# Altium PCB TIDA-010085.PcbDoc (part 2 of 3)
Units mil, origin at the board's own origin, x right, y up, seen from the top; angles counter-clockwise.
Board outline 1968.5 x 2559.06 mil, 4 copper layers (Top Layer, Signal Layer 1, Signal Layer 2, Bottom Layer), stack 5.6 mil thick; 254 components, 133 nets, 771 pads, 156 vias.
Unrouted connection lines stored in the file: 2.
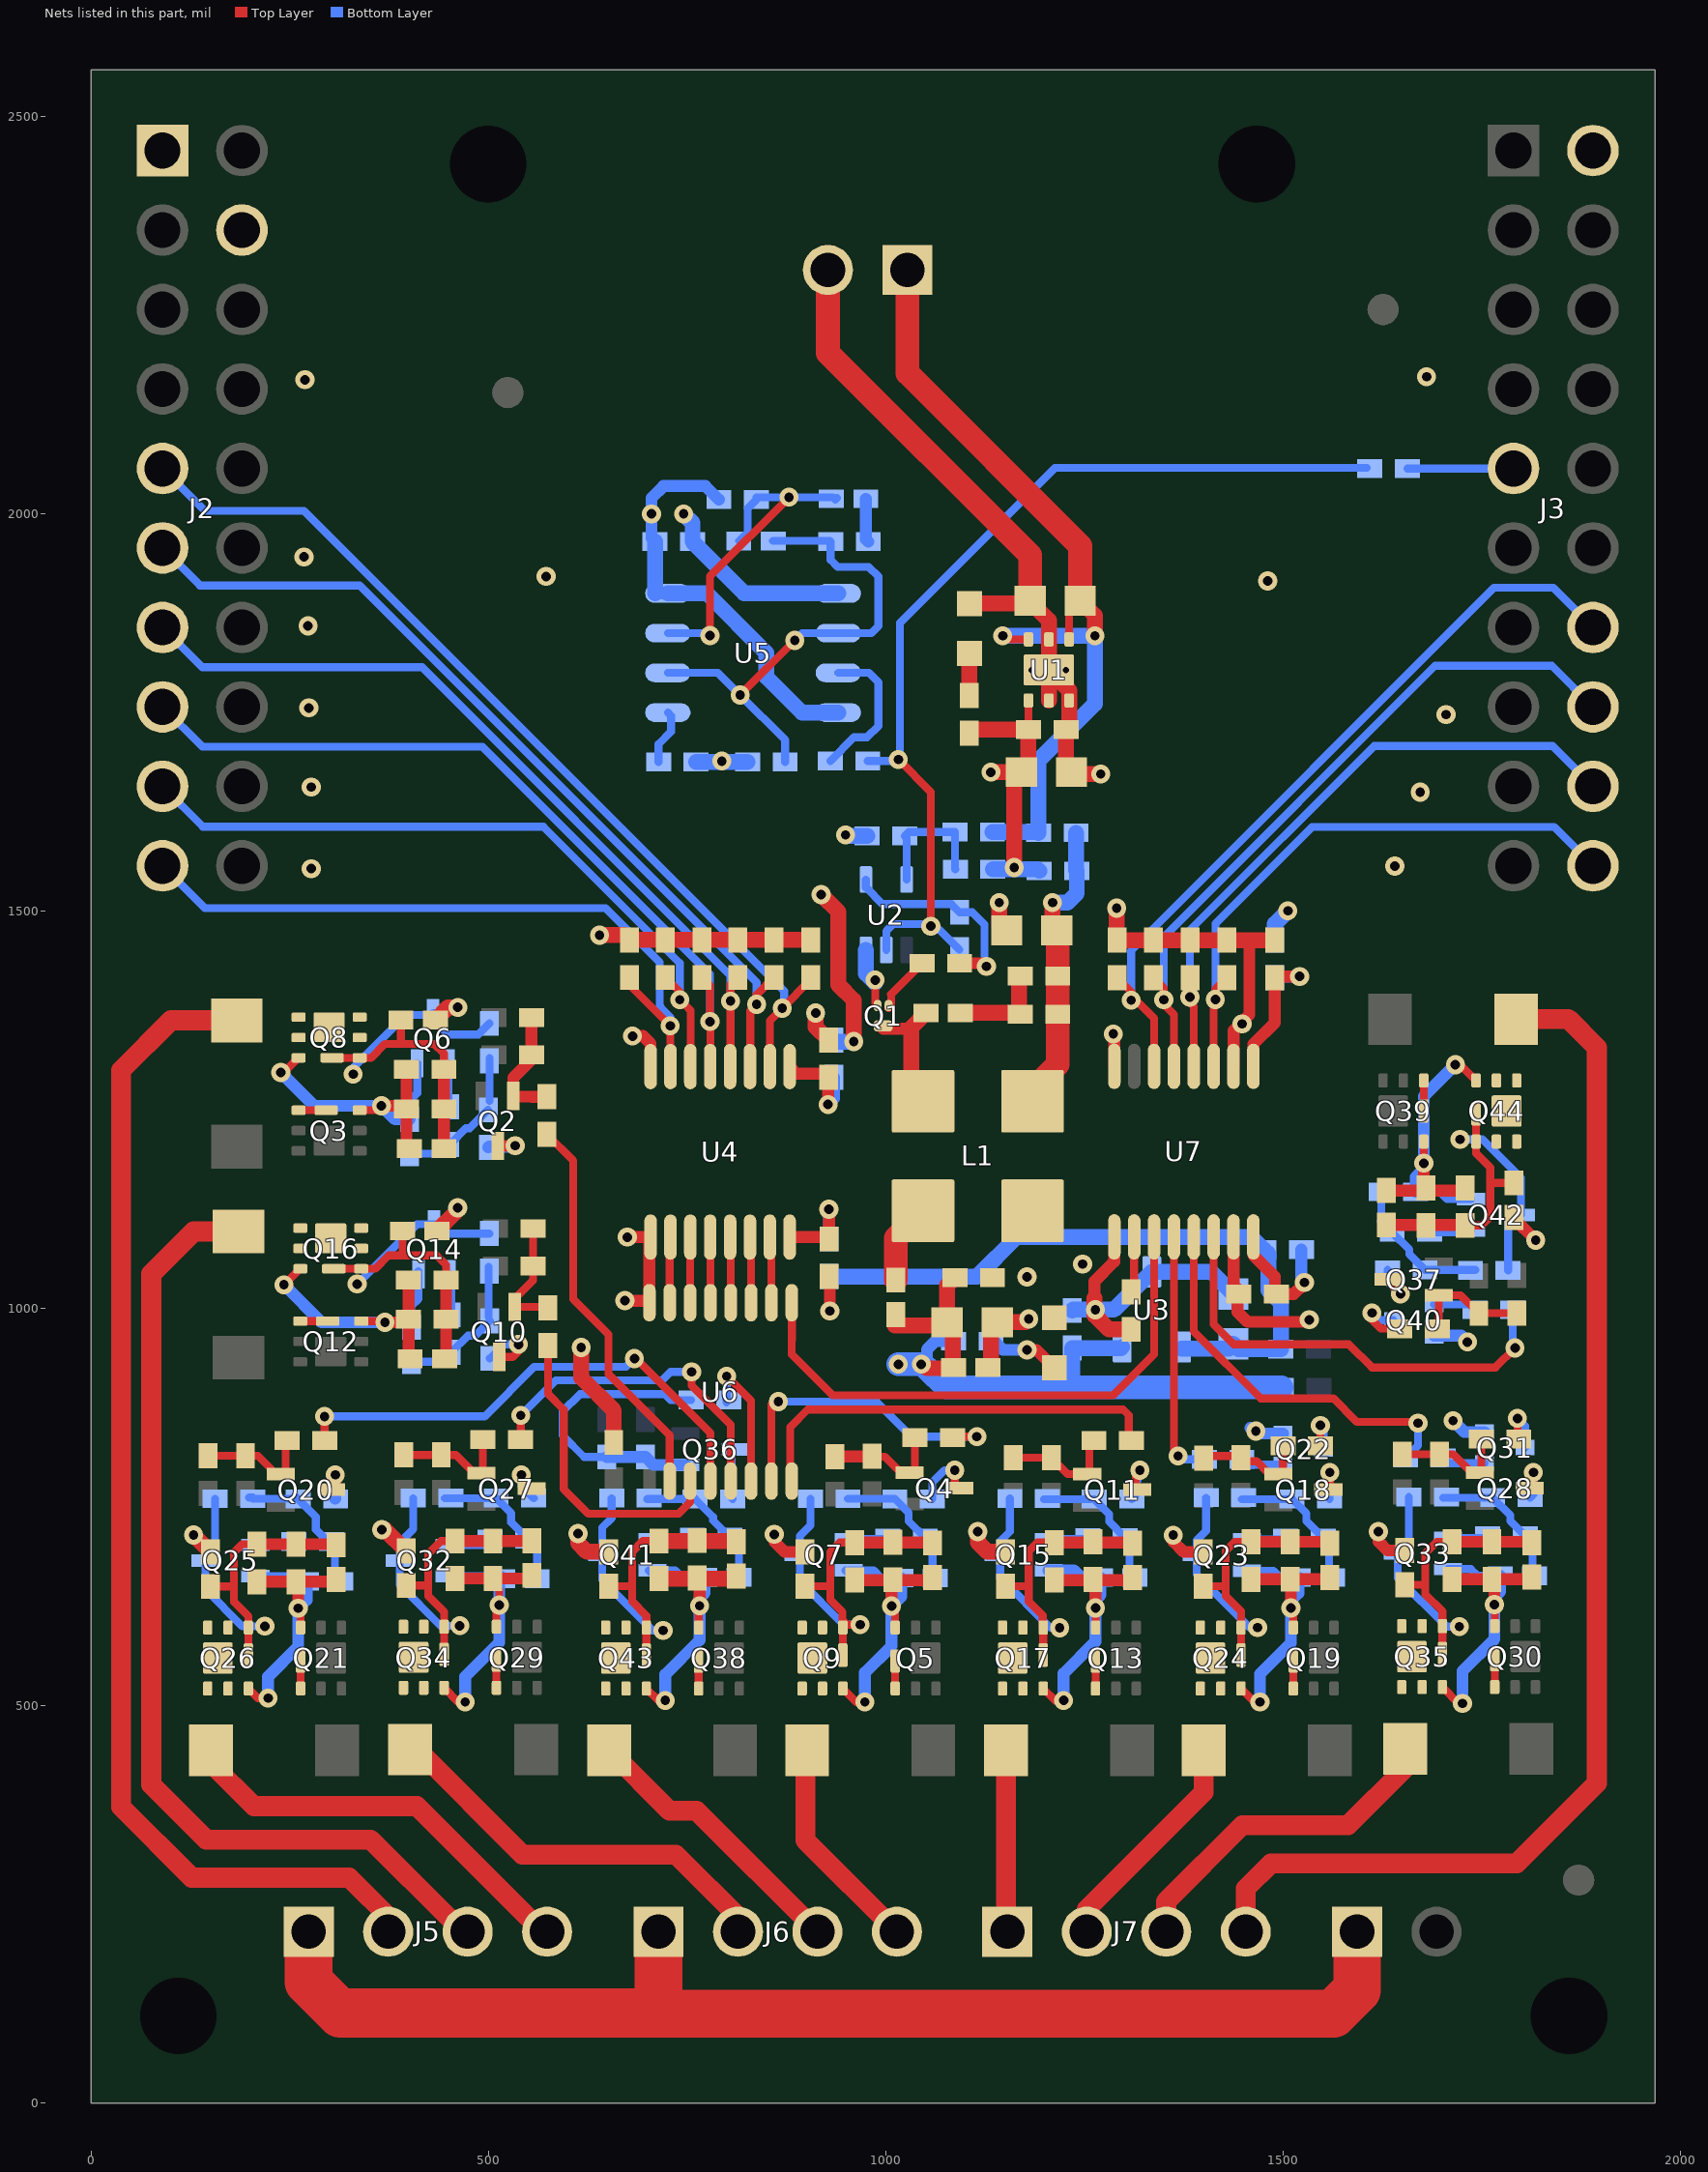
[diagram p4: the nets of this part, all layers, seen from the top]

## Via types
v1: diameter 24, hole 12, Top Layer to Bottom Layer, tented both sides, 144 vias
v2: diameter 40, hole 20, Top Layer to Bottom Layer, 10 vias
v3: diameter 19.68, hole 7.87, Top Layer to Bottom Layer, 2 vias

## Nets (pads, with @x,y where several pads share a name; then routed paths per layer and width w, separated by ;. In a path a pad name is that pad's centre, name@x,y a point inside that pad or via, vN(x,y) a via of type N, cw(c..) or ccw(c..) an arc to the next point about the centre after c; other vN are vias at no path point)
3V3: C3.1 C6.1 C12.2 J2.1 R1.2 R2.1 R10.1 R14.2 R16.2 R24.2 U1.1 U5.4 U5.8 | length 1179.7
  Top Layer w10: C6.1@1179.79,1728.71 U1.1@1179.79,1765.29
  Top Layer w20: v1(919,1521) 940.64,1499.36 940.64,1407.36 960,1388 v1(960,1336) ; R1.2@1105.38,1724.06 1110,1728.68 C6.1@1179.75,1728.68 C3.1@1179.75,1677.05 ; v1(1132.51,1675) C3.1@1151.81,1675 ; v1(1161.92,1555) 1161.92,1666.01 C3.1@1170.91,1675
  Bottom Layer w15: U5.8@709.89,1900 U5.8@726,1900 ; C12.2@709.89,1965 705.51,1969.38 v1(705.51,2000) 705.51,2020 720.51,2035 773.27,2035 R16.2@790.27,2018
  Bottom Layer w20: J2.1@90.08,2457.17 J2.1@101.3,2457.17 ; U5.8@709.89,1900 C12.2@709.89,1965 ; U5.8@726,1900 775,1900 850,1825 850,1795 895,1750 U5.4@940.57,1750 ; R14.2@935,1338.1 937.1,1336 v1(960,1336) ; R10.1@1134.97,1552.82 1191.29,1552.82 R2.1@1193.34,1550.76 ; R24.2@1489.83,1463.74 1489.83,1484.22 v1(1506.2,1500.58)
5V: C2.1 J1.1 R4.1 R11.1 U1.4 U1.6 | length 1100
  Top Layer w10: v1(1147.38,1846.68) 1151.99,1842.07 U1.6@1179.79,1842.07 ; U1.4@1230.97,1842.07 1230.97,1884.77 C2.1@1240.38,1894.18
  Top Layer w20: C2.1@1244.87,1890.68 1263.38,1872.18 v1(1263.38,1846.68)
  Top Layer w30: J1.1@1027.39,2307 1027.39,2177.24 1244.87,1959.77 C2.1@1244.87,1890.68
  Bottom Layer w20: R11.1@1134.48,1599.67 1191.54,1599.67 R4.1@1192.44,1598.76 1192.44,1690.19 1263.38,1761.12 v1(1263.38,1846.68) v1(1147.38,1846.68)
5V_ISO: C9.1 R9.2 R13.2 R25.2 U3.1 | length 839
  Bottom Layer w20: R13.2@929,1040.11 R13.2@928.73,1040.38 1115.38,1040.38 1165,1090 1460.39,1090 R25.2@1476.01,1074.38 1482,1068.39 1482,1023 1497.38,1007.62 R9.2@1497.38,949 1444.11,949 C9.1@1437.61,955.5 1431.86,949.76 U3.1@1372.4,949.76
12V_ISO: C1.2 C8.1 D1.1 D2.1 R3.2 R5.1 R8.1 U3.2 | length 881.7
  Top Layer w20: D1.1@1011.7,978.64 1073.34,978.64 C1.2@1077.5,982.8 ; v1@1052,925 D2.1@1084.36,925 ; D2.1@1085.35,925.98 D2.1@1084.36,925 ; R5.1@1087.24,1039.12 1077.5,1029.38 C1.2@1077.5,982.8 ; C1.2@1077.5,982.8 1084.36,975.94 D2.1@1084.36,925
  Bottom Layer w15: v1@1052,925 1052,948.53 1062.47,959 R3.2@1085.38,959
  Bottom Layer w20: 1233,901 1235,903 C8.1@1235,950.38 1296.22,950.38 U3.2@1297.6,951.76
  Bottom Layer w30: v1(1016,930) v1(1045,930) ; v1@1052,925 1076,901 1233,901 R8.1@1497.91,901
C: J4.1 J5.1 J6.1 | length 1934.1
  Top Layer w60: J5.1@274.13,216 274.13,152.78 311.91,115 ; 687.4,115 311.91,115 ; 714.24,141.84 J6.1@714.24,216 ; J4.1@1593.27,216 1593.27,142.67 1563.6,113 714.24,113 313.91,113 311.91,115
COIL-1: D12.1 J5.2 Q8.1 Q8.2 Q8.5 Q8.6 Q8.8 | length 1499.1
  Top Layer w25: D12.1@183.78,1362.45 183.39,1362.84 100.96,1362.84 38,1299.89 38,373 127,284 325,284 J5.2@379,230
COIL-2: D22.1 J5.3 Q16.1 Q16.2 Q16.5 Q16.6 Q16.8 | length 1248.4
  Top Layer w25: D22.1@185.83,1097.06 129.43,1097.06 76,1043.63 76,401 145,332 351.97,332 453.97,230 J5.3@479,230
COIL-3: D31.1 J5.4 Q26.1 Q26.2 Q26.5 Q26.6 Q26.8 | length 526.1
  Top Layer w25: D31.1@151.25,444.29 151.25,427.96 205.21,374 410,374 554,230 J5.4@579,230
COIL-4: D38.1 J6.2 Q34.1 Q34.2 Q34.5 Q34.6 Q34.8 | length 510.7
  Top Layer w25: D38.1@397.61,445.29 410.71,445.29 543,313 736.11,313 J6.2@819.11,230
COIL-5: D46.1 J6.3 Q43.1 Q43.2 Q43.5 Q43.6 Q43.8 | length 356.7
  Top Layer w25: D46.1@652.06,444.29 728.35,368 762.24,368 J6.3@914.24,216
COIL-6: D15.1 J6.4 Q9.1 Q9.2 Q9.5 Q9.6 Q9.8 | length 275.9
  Top Layer w25: D15.1@899.32,444.29 899.32,330.92 J6.4@1014.24,216
COIL-7: D23.1 J7.1 Q17.1 Q17.2 Q17.5 Q17.6 Q17.8 | length 229
  Top Layer w25: D23.1@1151.43,444.29 1151.43,217.7 J7.1@1153.13,216
COIL-8: D28.1 J7.2 Q24.1 Q24.2 Q24.5 Q24.6 Q24.8 | length 289.3
  Top Layer w25: J7.2@1253.13,216 1253.13,243.99 1400.32,391.18 D28.1@1400.32,444.29
COIL-9: D39.1 J7.3 Q35.1 Q35.2 Q35.5 Q35.6 Q35.8 | length 432.6
  Top Layer w25: J7.3@1353.13,216 1353.13,254.13 1448.86,349.86 1581.86,349.86 1653.78,421.78 D39.1@1653.78,446.11
COIL-10: D47.1 J7.4 Q44.1 Q44.2 Q44.5 Q44.6 Q44.8 | length 1596.3
  Top Layer w25: J7.4@1453.13,216 1453.13,270.13 1485,302 1794,302 1895,403 1895,1328.61 1859.01,1364.61 D47.1@1790.23,1364.61
GND: C2.2 C3.2 C4.2 C6.2 C7.2 C10.1 C12.1 C13.2 C14.2 C16.1 D3.1 J1.2 J2.4 J3.2 Q1.2 R18.1 R19.1 R20.1 R21.1 R22.1 R23.1 R28.1 R29.1 R30.1 R31.1 U1.2 U1.3 U1.5 U1.7@1205.38,1803.68 U2.3 U4.8 U5.1 U7.2 U7.8 | length 2187.6
  Top Layer w9.84: v1(986.83,1413.53) 986.83,1384.49 Q1.2@989.97,1381.35
  Top Layer w15: v1(681.57,1342.96) 694.96,1342.96 704.25,1333.67 704.25,1304.63 U4.8@704.3,1304.57 ; v1(1286.44,1345.67) 1287.78,1344.33 U7.8@1287.78,1304.82 ; U7.2@1437.78,1304.91 1437.78,1349.84 1457.8,1369.86 1457.8,1463.74
  Top Layer w20: v1(640,1470) 671.71,1470 R23.1@677.75,1463.96 R22.1@722.75,1463.96 R21.1@768.75,1463.96 R20.1@813.75,1463.96 R19.1@859.56,1463.96 R18.1@905.75,1463.96 ; v1(912,1372) 912,1354.29 C10.1@928.2,1338.1 ; D3.1@1105.38,1887.18 1175.38,1887.18 1179.88,1891.68 1205.38,1866.18 U1.5@1205.38,1842.07 U1.7@1205.38,1803.68 ; v1(1143,1511) 1143,1480.65 C4.2@1147.72,1475.92 ; U1.2@1205.38,1765.29 U1.7@1205.38,1803.68 ; v1(1270.7,1672.68) 1236.22,1672.68 C3.2@1233.9,1675 1227,1681.91 C6.2@1227,1728.68 1230.97,1732.65 U1.3@1230.97,1765.29 1230.97,1778.09 U1.7@1205.38,1803.68 ; v1(1290.83,1504) 1290.83,1464.1 R31.1@1291.2,1463.74 R30.1@1336.99,1463.74 R29.1@1383.2,1463.74 R28.1@1429.2,1463.74 1457.8,1463.74 C16.1@1489.83,1463.74
  Top Layer w30: J1.2@927.39,2307 927.39,2202.48 1181.88,1947.99 C2.2@1181.88,1890.68
  Bottom Layer w20: v1(745.89,2000) 757.13,1988.76 C12.1@757.13,1965 822.13,1900 U5.1@940.57,1900 ; C13.2@761.62,1688 C14.2@826.38,1688 ; v1(949.67,1596.12) 951.18,1594.61 C7.2@976.72,1594.61 ; U2.3@975.25,1451.32 975.25,1421.67 v1@986.83,1410.09
  other v1: 1448.63,1358.26 277.31,1553.63 1640.84,1556.85 1672.73,1649.98 277.31,1656.26 794,1689 1705.33,1747.55 274.31,1755.85 273.22,1858.99 1480.7,1915.64 572.73,1921.28 268.31,1945.85 269.31,2168.85 1680.7,2172.64
  other v3: 1183.72,1803.68 1227.03,1803.68
IN1: J2.19 R23.2 U4.7 | length 899.1
  Top Layer w10: R23.2@676.47,1415.44 R23.2@677.75,1416.72 677.75,1407.09 v1(729,1355.84) 729.3,1355.54 U4.7@729.3,1304.57 ; U4.7@729.8,1302.34 U4.7@729.8,1304.57
  Bottom Layer w10: J2.19@90.08,1557.17 143.26,1504 647.79,1504 715.88,1435.91 715.88,1381.25 717,1380.13 717,1378.81 729,1366.81 v1(729,1355.84)
IN2: J2.17 R22.2 U4.6 | length 899.5
  Top Layer w10: R22.2@722.75,1416.72 741,1398.47 v1(741,1388.75) ; v1@748,1382 754.8,1375.2 U4.6@754.8,1302.34
  Bottom Layer w10: J2.17@90.08,1657.17 140.84,1606.42 569.42,1606.42 741,1434.83 v1@741,1396.41
IN3: J2.15 R21.2 U4.5 | length 1006.5
  Top Layer w10: R21.2@768.75,1416.72 779,1406.47 v1(779,1361.2) ; U4.5@779.8,1302.34 v1@779.8,1361.2
  Bottom Layer w10: J2.15@90.08,1757.17 140.23,1707.03 492.85,1707.03 779,1420.88 v1(779,1361.2)
IN4: J2.13 R20.2 U4.4 | length 1046.4
  Top Layer w10: U4.4@804.8,1302.34 v1(804.8,1387) 804.8,1407.77 R20.2@813.75,1416.72
  Bottom Layer w10: J2.13@90.08,1857.17 140.26,1807 416.92,1807 804.8,1419.11 v1(804.8,1387)
IN5: J2.11 R19.2 U4.3 | length 1128.4
  Top Layer w10: U4.3@829.8,1302.34 829.8,1374.82 v1(837.76,1382.78) 837.76,1394.92 R19.2@859.56,1416.72
  Bottom Layer w10: J2.11@90.08,1957.17 137.26,1910 337.96,1910 837.76,1410.2 v1(837.76,1382.78)
IN6: J2.9 R18.2 U4.2 | length 1216.2
  Top Layer w10: U4.2@854.3,1304.57 854.3,1362.22 v1(870,1377.92) R18.2@905.75,1413.67 ; R18.2@905.75,1407.29 R18.2@905.75,1413.67 ; R18.2@905.75,1416.72 R18.2@905.75,1413.67
  Bottom Layer w10: J2.9@90.08,2057.17 143.59,2003.67 268.33,2003.67 872.32,1399.68 v1@872.32,1377.92
IN7: J3.14 R31.2 U7.6 | length 987.5
  Top Layer w10: R31.2@1291.2,1416.49 1309,1398.69 v1(1309,1388.13) 1314.87,1388.13 1337.78,1365.22 U7.6@1337.78,1304.91
  Bottom Layer w10: v1(1309,1388.13) 1309,1450.53 1765.47,1907 1840.26,1907 J3.14@1890.08,1857.17
IN8: J3.16 R30.2 U7.5 | length 903.9
  Top Layer w10: R30.2@1336.99,1416.49 1350,1403.48 v1(1350,1388.75) 1350,1382.78 1362.78,1370 U7.5@1362.78,1304.91
  Bottom Layer w10: v1(1350,1388.75) 1350,1467.49 1691.41,1808.9 1838.36,1808.9 J3.16@1890.08,1757.17
IN9: J3.18 R29.2 U7.4 | length 822.2
  Top Layer w10: R29.2@1383.2,1416.49 1382.83,1416.13 v1(1382.83,1392.12) 1382.83,1385.12 1387.78,1380.17 U7.4@1387.78,1304.91
  Bottom Layer w10: v1(1382.83,1392.12) 1382.83,1476.28 1614.46,1707.9 1839.36,1707.9 J3.18@1890.08,1657.17
IN10: J3.20 R28.2 U7.3 | length 750.4
  Top Layer w10: U7.3@1412.78,1304.91 v1@1412.78,1380.78 ; v1(1415,1388.97) 1415,1402.3 R28.2@1429.2,1416.49
  Bottom Layer w10: v1(1415,1388.97) 1415,1484.4 1536.6,1606 1841.26,1606 J3.20@1890.08,1557.17
ISO_GND: C1.1 C8.2 C9.2 C11.2 C15.2 C17.2 D2.2 D5.1 D10.1 D13.1 D18.1 D19.1 D26.1 D29.1 D34.1 D35.1 D42.1 D43.1 L1.4 Q22.2 Q31.2 Q40.2 R5.2 R27.2 U3.3 U4.9 U6.8 U7.9 U7.15 | length 1624.2
  Top Layer w15: v1(672,1010) 700.25,1010 U6.8@702.78,1007.47 702.78,1088.48 U4.9@704.3,1090.01 v1@675.01,1090.01 ; v1(860,716) 860,707 873.06,693.94 D13.1@898.65,693.94 ; C11.2@928.73,1040.38 929.89,1039.22 v1(929.89,997) ; R5.2@1134.48,1039.12 R5.2@1140.5,1039.12 ; 1262.98,1013.15 1262.98,1034.44 1287.78,1059.24 U7.9@1287.78,1090.25 ; v1@1362,719.29 v1(1362,715) 1362,706.94 1375,693.94 D26.1@1399.65,693.94 ; U7.15@1437.78,1090.25 1437.78,1029.82 1442.73,1024.87 1442.73,996.01 1455.43,983.31 1530.31,983.31 v1(1533,986) ; v1(1620,719.29) 1620,707.11 1631.35,695.77 D35.1@1653.11,695.77 ; D43.1@1792.53,1113 D43.1@1790.57,1114.95 1790.57,1113.43 v1(1818,1086)
  Top Layer w20: v1(129.25,715.27) D29.1@150.58,693.94 ; v1(366,722) 369.89,722 D34.1@396.94,694.94 ; D10.1@433.44,1363.12 449.44,1379.12 v1(461.78,1379.12) ; D18.1@435.48,1097.73 v1@458.16,1120.41 ; v1(613,717) 613,705 624.06,693.94 D42.1@651.4,693.94 ; v1(617,951) 617,913 658,872 C15.2@658,831.62 ; v1(1116,719.38) 1116,706 1128.06,693.94 D19.1@1150.76,693.94 ; D2.2@1132.51,925 1132.51,990.78 C1.1@1139.98,983.31 ; C1.1@1139.98,985.72 C1.1@1139.98,983.31 ; v1(1180.03,987) 1175.83,982.8 C1.1@1140.5,982.8 C1.1@1139.98,983.31 ; 1262.98,1013.15 1262.98,991.83 1280.9,973.91 R27.2@1308.93,973.91
  Bottom Layer w15: v1@1459,850 1466.03,842.97 Q22.2@1500.06,842.97 ; Q40.2@1690.16,965.92 1724.27,965.92 v1(1732.19,958) ; v1(1714,858.97) 1728.18,844.8 Q31.2@1753.52,844.8
  Bottom Layer w20: C8.2@1235,997.62 1235.99,998.61 v1(1264,998.61) 1287.36,998.61 U3.3@1335,1046.24 1409.86,1046.24 C9.2@1437.61,1018.5
  other v1: 1465.95,846 1178.03,1039.87 1248,1056 675,1090 461.7,1126.8
NetC4_1: C4.1 C5.1 L1.1 R2.2 R4.2 R6.2 | length 378
  Top Layer w20: v1(1210,1511) 1210,1476.64 C4.1@1216.62,1470.02
  Top Layer w30: L1.1@1184.9,1260.9 1185.1,1260.9 1185.1,1275.8 1216.62,1307.32 R6.2@1216.62,1370.29 C4.1@1216.62,1470.02
  Bottom Layer w20: v1(1210,1511) 1229,1511 1240.59,1522.59 R2.2@1240.59,1550.76 1239.69,1551.66 R4.2@1239.69,1598.76
NetC5_2: C5.2 D4.1 R6.1 | length 123.1
  Top Layer w15: R6.1@1167.67,1372 R6.1@1169.38,1370.29 ; C5.2@1167.67,1416.58 C5.2@1169.38,1418.29
  Top Layer w20: D4.1@1094,1372 1167.67,1372 C5.2@1167.67,1416.58
NetC7_1: C7.1 R10.2 R11.2 U2.5 | length 168.1
  Bottom Layer w10: U2.5@1026.43,1539.9 1026.43,1592.15 C7.1@1023.97,1594.61 1029.03,1599.67 R11.2@1087.24,1599.67 1087.24,1553.3 R10.2@1087.72,1552.82
NetC10_2: C10.2 R14.1 U4.1 | length 132.6
  Top Layer w15: U4.1@879.3,1304.63 888.21,1295.72 928.73,1295.72 927.56,1294.55 C10.2@927.56,1291.49 ; v1@926,1255.3 v1(927.56,1256.86) C10.2@927.56,1291.49 ; C10.2@928.2,1290.85 C10.2@927.56,1291.49
  Bottom Layer w15: v1(927.56,1256.86) 935,1264.3 R14.1@935,1290.85
NetC11_1: C11.1 R13.1 U4.16 | length 125.2
  Top Layer w15: U4.16@879.3,1090.01 926.35,1090.01 C11.1@928.73,1087.62 v1(928.73,1125)
  Bottom Layer w15: R13.1@928.73,1087.62 v1(928.73,1125)
NetC13_1: C13.1 U5.5 | length 70.1
  Bottom Layer w10: C13.1@714.38,1688 714.38,1710.38 730,1726 730,1746 U5.5@726,1750
NetC14_1: C14.1 D6.1 R17.2 U5.2 U5.6 | length 646.6
  Top Layer w10: v1(817,1772) v1(885.73,1840.73)
  Bottom Layer w10: U5.6@726,1800 789,1800 v1(817,1772) 873.62,1715.38 C14.1@873.62,1688 ; D6.1@858.51,1966 929.89,1966 R17.2@930.89,1965 930.89,1942.11 939.73,1933.27 978.73,1933.27 991,1921 991,1859 982,1850 U5.2@940.57,1850 895,1850 v1(885.73,1840.73)
NetC16_2: C16.2 R24.1 U7.1 | length 192
  Top Layer w15: U7.1@1462.78,1304.91 1462.78,1332.75 1489.83,1359.8 C16.2@1489.83,1411.49 ; C16.2@1485.83,1415.49 C16.2@1489.83,1411.49 ; v1(1521,1418) 1491.34,1418 C16.2@1489.83,1416.49 C16.2@1489.83,1411.49
  Bottom Layer w15: R24.1@1489.83,1416.49 1491.34,1418 v1(1521,1418)
NetC17_1: C17.1 R25.1 U7.16 | length 157.6
  Top Layer w15: U7.16@1462.78,1090.25 1462.78,1067.22 1489.97,1040.03 C17.1@1489.97,1024.87 ; C17.1@1491.62,1018.49 1513.7,1018.49 v1@1525,1029.79
  Bottom Layer w15: R25.1@1523.26,1074.38 1523.26,1036.74 v1(1527,1033)
NetC18_2: C18.2 Q2.1 R32.1 R35.2 | length 169.7
  Top Layer w15: R32.1@554.4,1366.12 C18.2@554.4,1319.12 554.4,1313.4 531.47,1290.47 Q2.1@531.47,1267.61 532.34,1266.74 554.77,1266.74 R35.2@573.78,1266.74 ; 554.77,1266.24 R35.2@573.78,1266.24
NetC19_2: C19.2 Q4.1 R33.1 R37.2 | length 155.7
  Top Layer w10: C19.2@979.12,813.84 C19.2@982.53,813.84 ; C19.2@982.86,814.17 C19.2@982.53,813.84 ; Q4.1@1026.97,794.64 1036.95,794.64 R37.2@1036.95,837.88 ; Q4.1@1029.97,793.64 1019.2,793.64 999,813.84 C19.2@982.53,813.84
  Top Layer w15: R33.1@936.33,813.84 C19.2@979.12,813.84
NetC20_1: C20.1 D8.1 D11.1 Q3.3 Q6.2 Q8.3 R39.2 | length 459.3
  Top Layer w10: v1(239.08,1297.13) 242.39,1297.13 260.78,1315.53 Q8.3@261.4,1315.53 Q8.3@262.31,1315.53 ; Q3.3@338.17,1249.71 365.19,1249.71 365.65,1250.17 v1(365.65,1255.3)
  Top Layer w15: v1(365.65,1255.3) 393.03,1255.3 C20.1@397.03,1251.3 ; R39.2@397.03,1301.3 C20.1@397.03,1251.3 ; D11.1@400.99,1201.3 397.03,1205.27 C20.1@397.03,1251.3
  Bottom Layer w10: D8.1@401.29,1238.3 401.29,1261.55 410.74,1271 Q6.2@410.74,1308.8
  Bottom Layer w15: v1(239.08,1297.13) 280.92,1255.3 v1(365.65,1255.3) 382.65,1238.3 D8.1@401.29,1238.3
NetC20_2: C20.2 D10.2 D11.2 Q3.4 Q3.7 Q6.3 Q8.4 Q8.7 R39.1 R41.1 | length 566.9
  Top Layer w10: Q3.4@261.4,1249.71 Q3.7@296.04,1249.71 ; Q8.7@303.52,1315.53 Q8.4@338.17,1315.53 352.53,1315.53 370,1333 389,1333 ; D10.2@390.13,1363.12 390.13,1334.13 389,1333 ; R39.1@444.27,1301.3 444.27,1320.73 432,1333 389,1333
  Top Layer w15: D11.2@444.27,1201.33 R39.1@444.27,1301.3
  Bottom Layer w10: v1(330,1295) 330,1302.99 396.62,1369.61 Q6.3@429.78,1369.61 ; Q6.3@430.43,1371.8 429.78,1371.15 Q6.3@429.78,1369.61 ; R41.1@501.65,1358.92 487.7,1344.98 448.51,1344.98 429.78,1363.71 Q6.3@429.78,1369.61
NetC21_1: C21.1 D9.1 D14.1 Q5.3 Q7.2 Q9.3 R42.2 | length 445.7
  Top Layer w10: Q9.3@946.24,521.9 963.14,505 v1(974,505) ; v1(1007.51,625.64) 1012.06,621.08 Q5.3@1012.06,598.67
  Top Layer w15: C21.1@961,658.38 R42.2@1008.5,658.38 ; v1(1007.51,625.64) 1007.51,657.39 R42.2@1008.5,658.38 ; R42.2@1009,658.88 R42.2@1008.5,658.38 ; D14.1@1059,661.85 1055.53,658.38 R42.2@1008.5,658.38
  Bottom Layer w10: Q7.2@949.24,670.6 Q7.2@952.19,667.65 ; Q7.2@953.5,670.6 985,670.6 994.6,661 D9.1@1019.35,661
  Bottom Layer w15: v1(974,505) 974,542 1007.51,575.51 v1(1007.51,625.64) 1019.35,637.47 D9.1@1019.35,661
NetC21_2: C21.2 D13.2 D14.2 Q5.4 Q5.7 Q7.3 Q9.4 Q9.7 R42.1 R43.1 | length 572.4
  Top Layer w10: D13.2@898.65,650.64 929.02,650.64 930.38,652 ; Q9.7@946.24,564.03 Q9.4@946.24,598.67 945.72,599.2 945.72,608.1 ; C21.2@961,705.62 942.15,705.62 930.38,693.85 930.38,652 ; v1(968,602.34) 951.48,602.34 945.72,608.1 ; Q5.4@1011.08,520.92 Q5.4@1012.06,521.9 Q5.7@1012.06,556.55 ; 930.38,652 930.38,633.62 945.72,618.28 945.72,608.1
  Top Layer w15: C21.2@961,705.62 1058.53,705.62 D14.2@1059,705.15
  Bottom Layer w10: Q7.3@890.5,690.29 Q7.3@892.15,690.29 ; R43.1@905.38,760.77 905.38,727.25 892.15,714.03 Q7.3@892.15,690.29 ; v1(968,602.34) 946.95,602.34 892.15,657.13 Q7.3@892.15,690.29
NetC22_2: C22.2 Q10.1 R44.1 R48.2 | length 150.3
  Top Layer w10: R44.1@556.45,1100.73 C22.2@556.45,1053.73 556.45,1035.45 533.51,1012.51 Q10.1@533.51,1002.23 573.74,1002.23 R48.2@575.19,1000.77
NetC23_2: C23.2 Q11.1 R45.1 R49.2 | length 144.8
  Top Layer w10: R45.1@1160.56,812.41 C23.2@1208.56,812.41 1229.2,791.76 Q11.1@1253.68,791.76 ; Q11.1@1256.27,791.97 1256.27,832.41 R49.2@1258.14,834.29
NetC24_1: C24.1 D16.1 D20.1 Q12.3 Q14.2 Q16.3 R52.2 | length 440.9
  Top Layer w10: v1(242.91,1030) 243.3,1030 Q16.3@263.44,1050.14 ; Q12.3@340.21,984.32 363.77,984.32 365.29,982.8 v1(370.08,982.8)
  Top Layer w15: v1(370.08,982.8) 395.72,982.8 C24.1@399.72,986.8 ; R52.2@399.72,1035.8 C24.1@399.72,986.8 ; D20.1@401.69,936.8 399.72,938.76 C24.1@399.72,986.8
  Bottom Layer w10: D16.1@403.35,976.45 403.35,1003.35 412.14,1012.14 Q14.2@412.14,1043.3 ; Q14.2@409.19,1044.19 Q14.2@412.14,1047.14
  Bottom Layer w15: v1(242.91,1030) 290.12,982.8 v1(370.08,982.8) D16.1@399.14,982.8
NetC24_2: C24.2 D18.2 D20.2 Q12.4 Q12.7 Q14.3 Q16.4 Q16.7 R52.1 R54.1 | length 549.1
  Top Layer w10: Q12.4@262.46,985.3 Q12.4@263.44,984.32 Q12.7@298.09,984.32 ; Q16.7@305.57,1050.14 358,1050.14 374.86,1067 391,1067 ; D18.2@392.17,1097.73 392.17,1068.17 391,1067 ; R52.1@446.97,1035.8 446.97,1055.03 435,1067 391,1067
  Top Layer w15: D20.2@445,936.8 446.97,938.76 R52.1@446.97,1035.8
  Bottom Layer w10: v1(335,1031) 410.29,1106.29 Q14.3@431.83,1106.29 431.83,1094.42 R54.1@501.35,1094.42
NetC25_1: C25.1 D17.1 D21.1 Q13.3 Q15.2 Q17.3 R53.2 | length 436.6
  Top Layer w10: Q17.3@1198.35,521.9 1213.25,507 v1(1224,507) ; Q13.3@1264.17,598.67 v1(1264.17,623.27)
  Top Layer w15: C25.1@1212.3,658.38 R53.2@1262,658.38 ; R53.2@1261,659.38 R53.2@1262,658.38 ; v1(1264.17,623.27) 1264.17,656.21 R53.2@1262,658.38 ; D21.1@1311,661.47 1307.9,658.38 R53.2@1262,658.38
  Bottom Layer w15: Q15.2@1205.13,670.63 1237,670.63 1246,661.63 D17.1@1270.35,661.63 1270.35,639.68 1264.17,633.5 v1(1264.17,623.27) 1264.17,581.17 1224,541 v1(1224,507)
NetC25_2: C25.2 D19.2 D21.2 Q13.4 Q13.7 Q15.3 Q17.4 Q17.7 R53.1 R55.1 | length 536.2
  Top Layer w10: D19.2@1150.76,650.64 1179.75,650.64 1180.03,650.35 ; Q17.7@1198.35,564.03 Q17.4@1198.35,598.67 1197.7,599.33 1197.7,614 1180.03,631.66 1180.03,650.35 ; C25.2@1212.3,705.62 1190.91,705.62 1180.03,694.75 1180.03,650.35 ; 1264.17,531.29 Q13.7@1264.17,556.55
  Top Layer w15: C25.2@1212.3,705.62 1310.16,705.62 D21.2@1311,704.78
  Bottom Layer w10: Q15.3@1142.14,690.31 Q15.3@1144.24,690.31 ; R55.1@1156.38,761 1156.38,719.38 1144.27,707.27 Q15.3@1144.27,690.29 ; v1(1219,598.47) 1207.42,598.47 1144.27,661.63 Q15.3@1144.27,690.29
NetC26_2: C26.2 Q18.1 R56.1 R59.2 | length 150
  Top Layer w10: R56.1@1396.65,814.6 1443.34,814.6 1443.65,814.91 1450.56,808 1466.65,808 1482.68,791.97 Q18.1@1494.15,791.97 1500.08,797.9 R59.2@1500.08,827.23 ; R59.2@1494.15,827.23 R59.2@1494.15,832.41
NetC27_2: C27.2 Q20.1 R57.1 R61.2 | length 144.2
  Top Layer w10: R57.1@147.58,814.91 C27.2@194.58,814.91 210.09,814.91 233.21,791.79 Q20.1@239.08,791.79 ; Q20.1@245.08,791.97 245.08,832.41 R61.2@246.96,834.29
NetC28_1: C28.1 D24.1 D27.1 Q19.3 Q23.2 Q24.3 R63.2 | length 438.2
  Top Layer w10: Q24.3@1447.24,521.9 1464.14,505 v1(1471,505) ; v1(1509.93,623.2) 1513.06,620.08 Q19.3@1513.06,598.67
  Top Layer w15: R63.2@1460,659.38 C28.1@1509.13,659.38 ; C28.1@1509,659.51 C28.1@1509.13,659.38 ; v1(1509.93,623.2) 1509.93,658.57 C28.1@1509.13,659.38 ; D27.1@1559,661.47 1556.9,659.38 C28.1@1509.13,659.38
  Bottom Layer w10: Q23.2@1454.5,670.31 1488,670.31 1496.69,661.63 D24.1@1519.35,661.63
  Bottom Layer w15: v1(1471,505) 1471,540.3 1509.93,579.24 v1(1509.93,623.2) 1509.93,632.57 1519.35,641.98 D24.1@1519.35,661.63
NetC28_2: C28.2 D26.2 D27.2 Q19.4 Q19.7 Q23.3 Q24.4 Q24.7 R63.1 R65.1 | length 544.9
  Top Layer w10: D26.2@1399.65,650.64 1427.71,650.64 1428,650.35 ; Q24.7@1447.24,564.03 Q24.4@1447.24,598.67 1447.24,619.31 1428,638.55 1428,650.35 ; R63.1@1460,706.62 1439.62,706.62 1428,695 1428,650.35 ; Q19.4@1512.67,522.29 Q19.4@1513.06,521.9 Q19.7@1513.06,556.55
  Top Layer w15: R63.1@1460,706.62 1557.16,706.62 D27.2@1559,704.78
  Bottom Layer w10: R65.1@1403.38,762.11 1403.38,720.38 1391.5,708.5 Q23.3@1391.5,690 1391.5,665.5 1458.33,598.67 v1(1468,598.67)
NetC29_1: C29.1 D25.1 D30.1 Q21.3 Q25.2 Q26.3 R67.2 | length 423.7
  Top Layer w10: Q26.3@198.17,521.9 210.07,510 v1(223,510) ; v1(260.99,623.01) 263.99,620.01 Q21.3@263.99,598.67
  Top Layer w15: C29.1@208.98,656.38 D30.1@305.85,656.38 ; v1(260.99,623.01) R67.2@260.99,656.38 ; D30.1@308.94,656.38 D30.1@311.91,659.35
  Bottom Layer w10: Q25.2@207,663.31 264.86,663.31 D25.1@271.35,656.82
  Bottom Layer w15: v1(223,510) 223,537 260.99,574.99 v1(260.99,623.01) 271.35,633.37 D25.1@271.35,656.82
NetC29_2: C29.2 D29.2 D30.2 Q21.4 Q21.7 Q25.3 Q26.4 Q26.7 R67.1 R68.1 | length 543.2
  Top Layer w10: D29.2@150.58,650.35 179.96,650.35 ; Q26.7@198.17,564.03 Q26.4@198.17,598.67 198.17,612.83 180,631 180,693 190.62,703.62 C29.2@212.07,703.62 ; Q21.4@263.01,520.92 Q21.4@263.99,521.9 Q21.7@263.99,556.55
  Top Layer w15: C29.2@208.98,703.62 D30.2@307.85,703.62 ; D30.2@310.94,703.62 D30.2@311.91,702.65
  Bottom Layer w10: Q25.3@144.01,683 144.01,646.99 190.62,600.38 v1(219,600.38) ; Q25.3@156.38,686.48 R68.1@156.38,760.77
NetC30_2: C30.2 Q27.1 R69.1 R73.2 | length 150.1
  Top Layer w10: R69.1@393.94,815.91 C30.2@440.94,815.91 459.09,815.91 482.03,792.97 Q27.1@491.45,792.97 493.32,794.85 R73.2@493.32,835.29
NetC31_2: C31.2 Q28.1 R70.1 R74.2 | length 150.1
  Top Layer w10: R70.1@1650.11,816.73 C31.2@1697.11,816.73 1714.38,816.73 1737.32,793.8 Q28.1@1747.62,793.8 1749.49,795.67 R74.2@1749.49,836.11
NetC32_1: C32.1 D32.1 D36.1 Q29.3 Q32.2 Q34.3 R77.2 | length 443.5
  Top Layer w10: Q34.3@444.53,522.9 462.44,505 v1(471,505) ; R77.2@506,660.38 502.7,657.07 513.83,645.94 v1(513.83,627) 513.83,623.34 510.35,619.86 Q29.3@510.35,599.67
  Top Layer w15: C32.1@458,660.38 551.03,660.38 D36.1@555,664.35
  Bottom Layer w10: Q32.2@451.5,663.31 D32.1@515.03,663.31 ; D32.1@513.83,655.48 D32.1@518.35,660
  Bottom Layer w15: v1(471,505) 471,537 513.83,579.83 v1(513.83,627) D32.1@513.83,655.48 ; D32.1@515.03,663.31 D32.1@518.35,660
NetC32_2: C32.2 D34.2 D36.2 Q29.4 Q29.7 Q32.3 Q34.4 Q34.7 R77.1 R79.1 | length 548.8
  Top Layer w10: D34.2@396.94,651.64 424.46,651.64 424.59,651.5 ; Q34.7@444.53,565.03 444.53,618.35 424.59,638.3 424.59,651.5 ; C32.2@458,707.62 440.62,707.62 424.59,691.59 424.59,651.5 ; Q29.4@509.37,521.92 Q29.4@510.35,522.9 Q29.7@510.35,557.55
  Top Layer w15: C32.2@458,707.62 D36.2@555,707.65
  Bottom Layer w10: R79.1@405.74,761.47 405.74,722.74 388.5,705.5 Q32.3@388.5,683 388.5,652.5 440,601 v1(464.22,601)
NetC33_1: C33.1 D33.1 D37.1 Q30.3 Q33.2 Q35.3 R78.2 | length 445.1
  Top Layer w10: Q35.3@1700.7,523.73 1721.23,503.2 v1(1726,503.2) ; v1(1766,627.64) 1766,621.08 1766.52,620.55 Q30.3@1766.52,600.5
  Top Layer w15: R78.2@1713,659.38 C33.1@1763,659.38 ; v1(1766,627.64) 1766,656.38 C33.1@1763,659.38 ; D37.1@1813,662.35 1810.03,659.38 C33.1@1763,659.38
  Bottom Layer w10: Q33.2@1707.5,672.31 1736.5,672.31 1744.82,664 D33.1@1773.35,664
  Bottom Layer w15: v1(1726,503.2) 1726,544 1766,584 v1(1766,627.64) 1766,636.58 1773.35,643.93 D33.1@1773.35,664
NetC33_2: C33.2 D35.2 D37.2 Q30.4 Q30.7 Q33.3 Q35.4 Q35.7 R78.1 R80.1 | length 552.7
  Top Layer w10: D35.2@1653.11,652.46 1679.1,652.46 ; Q35.7@1700.71,565.85 1700.71,618.91 1679.1,640.52 1679.1,652.46 ; R78.1@1713,706.62 1693.62,706.62 1679.1,692.1 1679.1,652.46 ; Q30.4@1766.14,524.11 Q30.4@1766.52,523.73 Q30.7@1766.52,558.37
  Top Layer w15: R78.1@1713,706.62 1812.03,706.62 D37.2@1813,705.65
  Bottom Layer w10: R80.1@1658.38,763 1658.38,696.38 1654,692 Q33.3@1644.5,692 1644.5,661.07 1705.57,600 v1(1722,600)
NetC34_2: C34.2 Q36.1 R82.1 R86.2 | length 373.8
  Bottom Layer w10: R82.1@649,813.38 620.62,813.38 593.65,840.35 593.65,870.65 615.31,892.31 722.2,892.31 729.51,885 R86.2@755.38,885
  Bottom Layer w15: R82.1@649,813.38 C34.2@698,813.38 708.06,803.31 Q36.1@748.06,803.31
NetC35_2: C35.2 Q37.1 R83.1 R87.2 | length 150.8
  Top Layer w10: R87.2@1694.19,974.61 1696.07,976.48 Q37.1@1696.07,1016.92 1723.64,1016.92 C35.2@1746.57,993.99 1746.89,994.3 R83.1@1794.16,994.3
NetC36_1: C36.1 D40.1 D44.1 Q38.3 Q41.2 Q43.3 R90.2 | length 442.7
  Top Layer w10: Q43.3@698.99,521.9 713.89,507 v1(722.75,507) ; Q38.3@764.8,598.67 764.8,621.19 763,623 v1(766,626)
  Top Layer w15: C36.1@763,660.88 763.5,660.38 766,657.88 v1(766,626)
  Top Layer w20: R90.2@715,660.38 763.5,660.38 809.03,660.38 D44.1@812,663.35
  Bottom Layer w10: Q41.2@701.99,670.6 Q41.2@704.94,667.65 ; Q41.2@706.5,670.6 735.12,670.6 743.72,662 D40.1@772.35,662
  Bottom Layer w15: v1(722.75,507) 722.75,539.63 766,582.88 v1(766,626) 766,636 772.35,642.35 D40.1@772.35,662
NetC36_2: C36.2 D42.2 D44.2 Q38.4 Q38.7 Q41.3 Q43.4 Q43.7 R90.1 R92.1 | length 551.8
  Top Layer w10: D42.2@651.4,650.64 678.64,650.64 681,653 ; Q43.7@698.99,564.03 698.99,613.65 681,631.64 681,653 ; R90.1@715,707.62 694.62,707.62 681,694 681,653 ; Q38.4@763.82,520.92 Q38.4@764.8,521.9 Q38.7@764.8,556.55
  Top Layer w20: R90.1@715,707.62 811.03,707.62 D44.2@812,706.65
  Bottom Layer w10: R92.1@655.38,761.47 655.38,736.48 643.5,724.6 Q41.3@643.5,690.29 643.5,658.53 700.03,602 707.03,595 v1(720,595)
NetC37_1: C37.1 D41.1 D45.1 Q39.3 Q42.2 Q44.3 R91.2 | length 448.2
  Top Layer w10: v1(1677.16,1183) Q39.3@1677.16,1210.22 ; v1(1717,1307) 1722.98,1307 Q44.3@1742.98,1286.99
  Top Layer w15: D45.1@1630,1148.65 1725.76,1148.65 C37.1@1729,1151.9 ; v1(1677.16,1183) 1677.16,1154.73 R91.2@1680,1151.9
  Bottom Layer w10: D41.1@1667,1147 1697.09,1147 1706.41,1137.69 Q42.2@1736.5,1137.69
  Bottom Layer w15: D41.1@1667,1147 1667,1165.45 1677.16,1175.61 v1(1677.16,1183) 1677.16,1267.16 v1(1717,1307)
NetC37_2: C37.2 D43.2 D45.2 Q39.4 Q39.7 Q42.3 Q44.4 Q44.7 R91.1 R93.1 | length 567.8
  Top Layer w10: Q39.7@1677.16,1248.61 Q39.4@1677.16,1286.99 Q39.4@1677.55,1286.61 ; C37.2@1729,1104.65 1749.65,1104.65 1761,1116 1761,1158.66 ; Q44.7@1742.98,1244.87 Q44.4@1742.98,1210.22 1742.98,1195.4 1761,1177.38 1761,1158.66 ; D43.2@1790.57,1158.26 1761.4,1158.26 1761,1158.66
  Top Layer w15: D45.2@1630,1105.35 1728.3,1105.35 C37.2@1729,1104.65
  Bottom Layer w10: v1(1722.98,1213) 1751,1213 1799.5,1164.5 Q42.3@1799.5,1118 Q42.3@1791,1118 ; R93.1@1783.24,1048 1783.24,1110.24 Q42.3@1791,1118 ; Q42.3@1789,1118 Q42.3@1791,1118
NetD1_2: D1.2 L1.3 | length 101.2
  Top Layer w30: D1.2@1013,1036 1013,1089 L1.3@1047.1,1123.1
NetD3_2: D3.2 R1.1 | length 52.9
  Top Layer w20: R1.1@1105.38,1771.3 D3.2@1105.38,1824.18
NetD4_2: D4.2 L1.2 Q1.3 | length 132.1
  Top Layer w15: Q1.3@996.86,1352.33 1027.83,1352.33 1031.02,1352.33
  Top Layer w20: 1031.02,1352.33 D4.2@1050.69,1372 ; L1.2@1032.31,1277.71 1032.31,1347.86
NetD5_2: D5.2 R3.1 | length 93.8
  Top Layer w15: v1(1178.03,948) 1189.8,948 D5.2@1212.3,925.5
  Bottom Layer w15: R3.1@1133.62,962 1147.62,948 v1(1178.03,948)
NetD6_2: D6.2 D7.1 R16.1 U5.7 | length 439.8
  Top Layer w10: v1@785,1847 v1(779,1847) 779,1921.49 v1(878.51,2021)
  Bottom Layer w10: U5.7@726,1850 776,1850 v1(779,1847) ; D6.2@815.86,1966 826.51,1976.65 826.51,2007 R16.1@837.51,2018 ; R16.1@837.51,2021 v1(878.51,2021) 933.86,2021 936.86,2018 D7.1@938.86,2020
NetD7_2: D7.2 R17.1 | length 55.2
  Bottom Layer w15: D7.2@975.17,2019 975.17,1967.97 R17.1@978.13,1965
NetD8_2: D8.2 R34.2 R38.2 R41.2 | length 175.6
  Bottom Layer w10: D8.2@401.29,1194.99 439.96,1194.99 R38.2@451.65,1206.68 471.97,1227 476.88,1227 R34.2@499.96,1250.08 ; R34.2@501.78,1261.39 R41.2@501.78,1315.5
NetD9_2: D9.2 R36.2 R40.2 R43.2 | length 179.8
  Bottom Layer w10: R43.2@952.62,760.77 1011.39,760.77 R36.2@1011.69,760.47 1029,743.16 1029,732.52 R40.2@1050,711.52 1059,702.52 1059,664.65 D9.2@1062.65,661
NetD16_2: D16.2 R46.2 R50.2 R54.2 | length 182.8
  Bottom Layer w10: D16.2@403.35,933.14 441.59,933.14 R50.2@453.35,944.9 474.45,966 483.32,966 R46.2@502.01,984.69 ; R46.2@500.36,989.8 R54.2@500.36,1052.57
NetD17_2: D17.2 R47.2 R51.2 R55.2 | length 183
  Bottom Layer w10: R55.2@1199.38,760.29 R47.2@1262.52,760.29 1281.24,741.57 1281.24,732.07 R51.2@1301.62,711.68 1307,706.31 1307,668.28 D17.2@1313.65,661.63
NetD24_2: D24.2 R58.2 R62.2 R65.2 | length 183.3
  Bottom Layer w10: R65.2@1448.27,760.29 1511.23,760.29 R58.2@1511.41,760.47 1529.52,742.36 1529.52,732.63 R62.2@1550.62,711.52 1558,704.14 1558,666.28 D24.2@1562.65,661.63
NetD25_2: D25.2 R60.2 R64.2 R68.2 | length 201.3
  Bottom Layer w10: R68.2@199.2,762.29 R68.2@203.62,762.29 ; R68.2@203.62,760.77 257.22,760.77 258.74,762.29 R60.2@260.74,760.29 283.13,737.9 283.13,721.87 302,703 R64.2@306.75,703 ; R64.2@302.62,707.12 R64.2@306.75,703 ; R64.2@310.62,703 R64.2@306.75,703 ; D25.2@314.65,656.82 307,664.48 307,702.75 R64.2@306.75,703
NetD32_2: D32.2 R71.2 R75.2 R79.2 | length 187.4
  Bottom Layer w10: R79.2@445.56,761.29 445.75,761.47 R79.2@452.98,761.47 R71.2@509.98,761.47 528.87,742.59 528.87,730.91 R75.2@549.78,710 561.65,698.12 D32.2@561.65,660
NetD33_2: D33.2 R72.2 R76.2 R80.2 | length 182.1
  Bottom Layer w10: R80.2@1701.74,762.11 R72.2@1763.87,762.11 1786,739.98 1786,732.85 R76.2@1804.74,714.11 1814,704.85 1814,666.65 D33.2@1816.65,664
NetD40_2: D40.2 R84.2 R88.2 R92.2 | length 181.8
  Bottom Layer w10: R92.2@700.02,760.29 700.2,760.47 R84.2@760.38,760.47 783,737.85 783,733.52 R88.2@804.23,712.29 815.65,700.87 D40.2@815.65,662
NetD41_2: D41.2 R85.2 R89.2 R93.2 | length 184.6
  Bottom Layer w10: D41.2@1623.69,1147 1623.69,1110.18 1623.45,1109.93 R89.2@1637.38,1096 1659,1074.38 1659,1068.42 R85.2@1678.82,1048.61 R93.2@1741.95,1048.61
NetJ3_9: J3.9 R26.1 | length 133.5
  Bottom Layer w10: R26.1@1656.62,2057 1789.91,2057 J3.9@1790.08,2057.17
NetQ1_1: Q1.1 R7.2 | length 74.1
  Top Layer w9.84: Q1.1@1003.75,1377.92 1006.89,1381.06 1006.89,1395.65
  Top Layer w10: 1006.89,1395.65 R7.2@1045.85,1434.6
NetQ2_3: Q2.3 R34.1 | length 57.6
  Top Layer w15: Q2.3@511.59,1205.28 512.06,1204.81 533.81,1204.81 v1(534,1205)
  Bottom Layer w15: R34.1@499.96,1202.84 501.05,1203.92 532.92,1203.92 v1(534,1205)
NetQ4_3: Q4.3 R36.1 | length 78.3
  Top Layer w10: v1(1087.03,796.67) 1087.03,777.88 Q4.3@1089.96,774.95
  Bottom Layer w10: R36.1@1058.93,760.47 1058.93,781.37 1074.24,796.67 v1(1087.03,796.67)
NetQ6_1: Q6.1 R38.1 | length 55.5
  Bottom Layer w10: Q6.1@450.11,1308.8 450.11,1255.46 R38.1@451.65,1253.92
NetQ7_1: Q7.1 R40.1 | length 49.9
  Bottom Layer w10: Q7.1@953.5,709.97 1001.21,709.97 R40.1@1002.76,711.52
NetQ10_3: Q10.3 R46.1 | length 78.9
  Top Layer w10: Q10.3@513.83,939.23 530.7,939.23 538,946.53 v1(538,955)
  Bottom Layer w10: R46.1@502.01,937.45 519.56,955 v1(538,955)
NetQ11_3: Q11.3 R47.1 | length 69.1
  Top Layer w10: Q11.3@1316.67,772.08 1314.88,772.08 1314.88,791.55 v1(1320,796.67)
  Bottom Layer w10: R47.1@1309.76,760.29 1314.88,765.4 1314.88,781.81 1317.32,784.26 1317.32,793.99 v1(1320,796.67)
NetQ14_1: Q14.1 R50.1 | length 51.9
  Bottom Layer w10: Q14.1@451.51,1043.3 453.35,1041.47 R50.1@453.35,992.14
NetQ15_1: Q15.1 R51.1 | length 49.9
  Bottom Layer w10: Q15.1@1205.13,710 1252.69,710 R51.1@1254.38,711.68
NetQ18_3: Q18.3 R58.1 | length 43.8
  Top Layer w10: Q18.3@1557.15,772.29 1558.98,774.12 v1@1558.98,791.76
  Bottom Layer w10: R58.1@1558.65,760.47 v1@1558.65,784
  other v1: 1559,794
NetQ20_3: Q20.3 R60.1 | length 55.6
  Top Layer w10: v1@303.02,790.85 v1(307.51,790.85)
  Top Layer w15: Q20.3@302.08,772.1 307.51,777.54 v1(307.51,790.85)
  Bottom Layer w15: R60.1@307.51,760.77 v1(307.51,790.85)
NetQ22_1: Q22.1 R66.2 | length 54.6
  Bottom Layer w10: R66.2@1448.27,810.29 1454.96,803.6 Q22.1@1500.06,803.6
NetQ22_3: Q22.3 R59.1 | length 60.7
  Top Layer w10: R59.1@1543.63,830.92 R59.1@1547,827.55 ; v1(1547,853) R59.1@1547,827.55 ; R59.1@1547.33,827.23 R59.1@1547,827.55
  Bottom Layer w10: Q22.3@1551.24,823.29 v1@1551.24,853.37
NetQ23_1: Q23.1 R62.1 | length 49.6
  Bottom Layer w10: Q23.1@1454.5,709.68 1501.54,709.68 R62.1@1503.38,711.52
NetQ25_1: Q25.1 R64.1 | length 50.2
  Bottom Layer w10: Q25.1@207,702.68 250.94,702.68 R64.1@255.38,707.12
NetQ27_3: Q27.3 R71.1 | length 58.6
  Top Layer w10: v1(541.7,790.85) 541.7,786.02 Q27.3@554.44,773.29
  Bottom Layer w10: v1(541.7,790.85) 541.7,776.99 R71.1@557.23,761.47
NetQ28_3: Q28.3 R72.1 | length 56.6
  Top Layer w10: Q28.3@1810.61,775.44 Q28.3@1810.61,774.11 1815.11,778.62 v1(1815.11,794)
  Bottom Layer w10: R72.1@1811.11,762.11 1815.11,766.11 v1(1815.11,794)
NetQ31_1: Q31.1 R81.2 | length 54.6
  Bottom Layer w10: R81.2@1701.74,812.11 1708.42,805.43 Q31.1@1753.52,805.43
NetQ31_3: Q31.3 R74.1 | length 67.3
  Top Layer w10: v1(1795.08,861.91) 1795.08,837.77 R74.1@1796.74,836.11
  Bottom Layer w10: v1(1795.08,861.91) 1804.71,852.28 Q31.3@1804.71,825.11
NetQ32_1: Q32.1 R75.1 | length 54.1
  Bottom Layer w10: Q32.1@451.5,702.68 495.22,702.68 R75.1@502.53,710
NetQ33_1: Q33.1 R76.1 | length 51
  Bottom Layer w10: Q33.1@1707.5,711.68 1755.07,711.68 R76.1@1757.49,714.11
NetQ36_3: Q36.3 R84.1 | length 63.3
  Bottom Layer w10: Q36.3@806.5,823.29 806.5,761.6 R84.1@807.62,760.47
NetQ37_3: Q37.3 R85.1 | length 61.7
  Top Layer w10: Q37.3@1633.08,1036.61 1633.08,1033.27 v1(1647.86,1018.49)
  Bottom Layer w10: R85.1@1631.57,1048.61 1631.57,1033.8 1646.88,1018.49 v1(1647.86,1018.49)
NetQ40_1: Q40.1 R94.2 | length 54.6
  Bottom Layer w10: Q40.1@1690.16,1005.29 1735.27,1005.29 R94.2@1741.95,998.61
NetQ40_3: Q40.3 R87.1 | length 78.8
  Top Layer w10: v1(1612,994.68) 1612,985.91 1623.05,974.87 R87.1@1646.69,974.87
  Bottom Layer w10: v1(1612,994.68) 1621.08,985.61 Q40.3@1638.98,985.61
NetQ41_1: Q41.1 R88.1 | length 51.4
  Bottom Layer w10: Q41.1@706.5,709.97 754.67,709.97 R88.1@756.99,712.29
NetQ42_1: Q42.1 R89.1 | length 52.8
  Bottom Layer w10: R89.1@1684.62,1096 1734.19,1096 Q42.1@1736.5,1098.31
NetR7_1: R7.1 R12.2 U2.4 | length 267.9
  Top Layer w15: R7.1@1093.09,1434.6 1123,1434.6 v1(1127,1430.61)
  Bottom Layer w10: U2.4@975.25,1539.9 975.25,1529.91 996.15,1509 1082.75,1509 R12.2@1092.98,1498.77 1109.18,1498.73 1124.39,1483.51 1124.39,1433.22 v1(1127,1430.61)
NetR15_1: R15.1 U5.3 | length 189.1
  Bottom Layer w10: R15.1@930.38,1689 960.38,1719 976.72,1719 991,1733.28 991,1788 979,1800 U5.3@940.57,1800
NetR27_1: R27.1 U7.10 | length 55.6
  Top Layer w10: R27.1@1312.78,1034.74 U7.10@1312.78,1090.34
NetU4_10: U4.10 U6.7 | length 83
  Top Layer w10: U6.7@728.37,1007.47 U4.10@728.37,1090.4 ; U4.10@729.3,1090.01 U4.10@729.37,1089.94
NetU4_11: U4.11 U6.6 | length 83.3
  Top Layer w10: U6.6@753.96,1007.47 U4.11@753.96,1089.81 ; U4.11@754.3,1090.01 U4.11@754.96,1089.35
NetU4_12: U4.12 U6.5 | length 83.5
  Top Layer w10: U4.12@779.3,1090.01 U4.12@780.55,1088.76 ; U6.5@779.55,1007.47 U4.12@779.55,1089.22
NetU4_13: U4.13 U6.4 | length 83.8
  Top Layer w10: U4.13@804.3,1090.01 U4.13@806.14,1088.17 ; U6.4@805.14,1007.47 U4.13@805.14,1088.63
NetU4_14: U4.14 U6.3 | length 84
  Top Layer w10: U4.14@829.3,1090.01 U4.14@831.73,1087.58 ; U6.3@830.73,1007.47 U4.14@830.73,1088.04
NetU4_15: U4.15 U6.2 | length 84.3
  Top Layer w10: U4.15@854.3,1090.01 U4.15@857.32,1086.98 ; U6.2@856.32,1007.47 U4.15@856.32,1087.45
NetU6_1: U6.1 U7.11 | length 757.7
  Top Layer w10: 882,961 882,1007.38 U6.1@881.91,1007.47 881.91,942.35 933.26,891 1286,891 1337.78,942.78 U7.11@1337.78,1090.25
OUT1: R35.1 U6.10 | length 500.5
  Top Layer w10: R35.1@573.78,1219.5 607,1186.28 607,1012 651.4,967.6 651.4,917.6 728.37,840.63 U6.10@728.37,783.06
OUT2: R48.1 U6.11 | length 393.2
  Top Layer w10: R48.1@575.19,953.53 575.19,892.81 595,873 595,773 626,742 739.68,742 753.96,756.28 U6.11@753.96,783.06
OUT3: R61.1 U6.12 | length 645.1
  Top Layer w10: v1(294,864.36) 294,834.49 R61.1@294.2,834.29 ; v1(684,937.2) 685.8,937.2 779.55,843.45 U6.12@779.55,783.06
  Bottom Layer w10: v1(294,864.36) 495.36,864.36 557.67,926.67 673.47,926.67 v1(684,937.2)
OUT4: R73.1 U6.13 | length 425.9
  Top Layer w10: R73.1@540.56,835.29 541,835.72 v1(541,865.72) ; v1(755.94,920.36) 755.94,903.06 805.14,853.86 U6.13@805.14,783.06
  Bottom Layer w10: v1(541,865.72) 584.94,909.67 718.67,909.67 729.36,920.36 v1(755.94,920.36)
OUT5: R86.1 U6.14 | length 177.8
  Top Layer w10: v1(800,915) 830.73,884.27 U6.14@830.73,783.06
  Bottom Layer w10: R86.1@799.62,882 800,882.38 v1(800,915)
OUT6: R37.1 U6.15 | length 405.8
  Top Layer w10: U6.15@856.32,783.06 856.32,879.32 860,883 v1(865,883) ; R37.1@1084.2,837.88 1085.2,838.88 v1(1114.93,838.88)
  Bottom Layer w10: v1(865,883) 988.36,883 1032.48,838.88 v1(1114.93,838.88)
OUT7: R49.1 U6.16 | length 554.9
  Top Layer w10: U6.16@881.91,783.06 880,784.97 880,851 902,873 1299,873 1306,866 1306,837.38 R49.1@1309.38,834 1318,834 1318,834.22 R49.1@1313.8,838.42
OUT8: R66.1 U7.12 | length 312.6
  Top Layer w10: U7.12@1362.78,1090.25 1362.78,819.82 v1(1368,814.6)
  Bottom Layer w10: v1(1368,814.6) 1372.32,810.29 R66.1@1401.03,810.29
OUT9: R81.1 U7.13 | length 502.8
  Top Layer w10: U7.13@1387.78,1090.25 1387.78,971.22 1472,887 1563.35,887 1592.9,857.45 1668.55,857.45 v1(1670,856)
  Bottom Layer w10: R81.1@1652,814.6 R81.1@1654.49,812.11 1670,827.62 v1(1670,856)
OUT10: R94.1 U7.14 | length 571.2
  Top Layer w10: U7.14@1412.78,1090.34 U7.14@1412.78,1090.25 1412.78,980.22 1438,955 1583,955 1612,926 1767.51,926 v1(1792,950.49)
  Bottom Layer w10: R94.1@1789.19,998.61 1789.19,953.3 v1(1792,950.49)
PWM: R12.1 R15.2 R26.2 U2.2 | length 1216
  Top Layer w10: v1(1016,1691) 1056.97,1650.03 v1(1056.97,1481.28) v1@1056.97,1477.28
  Bottom Layer w10: R15.2@977.62,1689 1014,1689 v1(1016,1691) ; U2.2@1000.84,1451.32 1000.84,1475.15 1009.69,1484 v1@1048.83,1484 ; v1@1018,1697 1018,1863 1213,2058 R26.2@1605.38,2058 ; v1@1067.23,1477.28 R12.1@1092.98,1451.53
